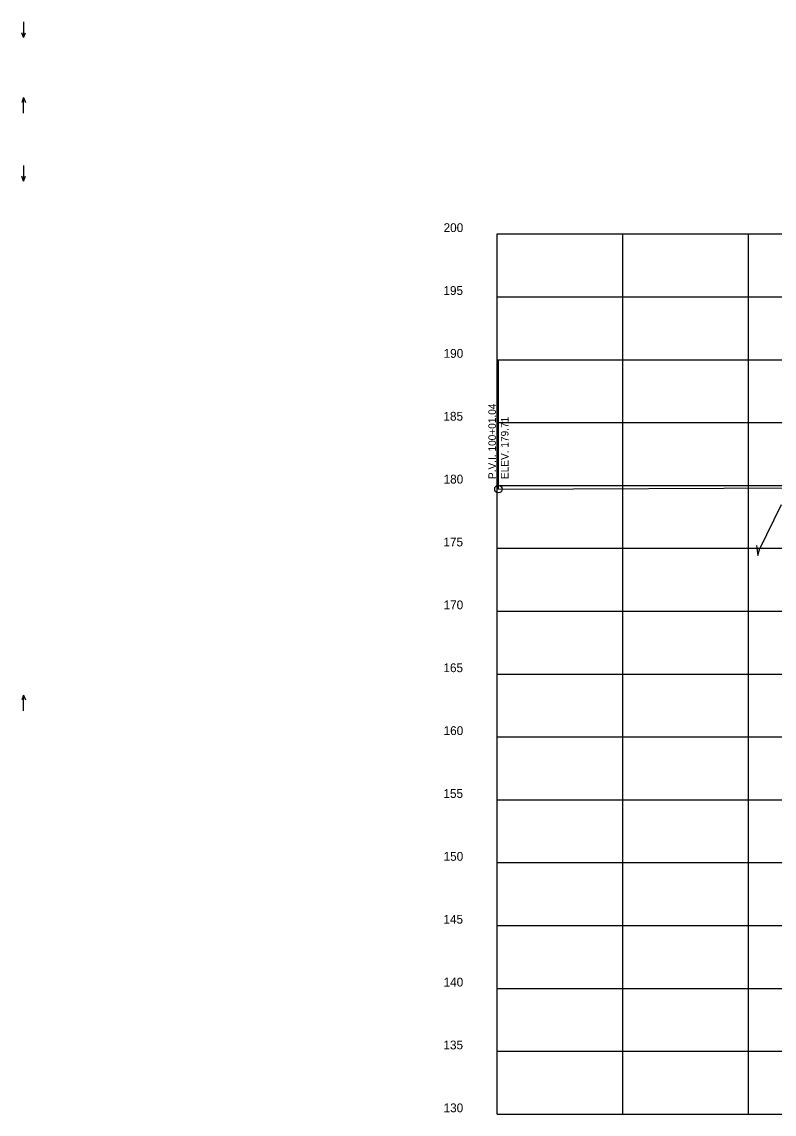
# Model space of a CAD drawing. Extents: x 915787 to 919910, y 133456 to 136717.
# Drawn here: x 916593 to 917192, y 135095 to 135964 of the extents above; entities that cross this region are included whole.
import ezdxf

# ---------------------------------------------------------------- set-up
doc = ezdxf.new("R2010")
doc.units = 0
for name, color, linetype in [('R_Axis', 7, 'Continuous'), ('R_Axis Annot', 7, 'Continuous'), ('R_Exist Surface', 7, 'Continuous'), ('R_Grid', 7, 'Continuous'), ('R_Vert Alg', 7, 'Continuous'), ('R_Vert Alg Annot', 7, 'Continuous'), ('R_Water Annot', 7, 'Continuous')]:
    doc.layers.add(name, color=color, linetype=linetype)

msp = doc.modelspace()

# ---------------------------------------------------------------- linework, layer by layer
at = {"layer": 'R_Axis'}
for q in [(916971.67, 135794.96), (919871.67, 135094.96)]:
    msp.add_line((916971.67, 135094.96), q, dxfattribs=at)
at = {"layer": 'R_Exist Surface'}
msp.add_lwpolyline([(917178.02, 135547.16), (917179.21, 135539.34), (917180.4, 135543.95), (917197.96, 135579.87)], dxfattribs=at)
at = {"layer": 'R_Grid'}
for p, q in [((916971.67, 135794.96), (919871.67, 135794.96)), ((916971.67, 135794.96), (919871.67, 135794.96)), ((917071.67, 135094.96), (917071.67, 135794.96)), ((917171.67, 135094.96), (917171.67, 135794.96)), ((916971.67, 135744.96), (919871.67, 135744.96)), ((916971.67, 135694.96), (919871.67, 135694.96)), ((916971.67, 135644.96), (919871.67, 135644.96)), ((916971.67, 135594.96), (919871.67, 135594.96)), ((916971.67, 135544.96), (919871.67, 135544.96)), ((916971.67, 135494.96), (919871.67, 135494.96)), ((916971.67, 135444.96), (919871.67, 135444.96)), ((916971.67, 135394.96), (919871.67, 135394.96)), ((916971.67, 135344.96), (919871.67, 135344.96)), ((916971.67, 135294.96), (919871.67, 135294.96)), ((916971.67, 135244.96), (919871.67, 135244.96)), ((916971.67, 135194.96), (919871.67, 135194.96)), ((916971.67, 135144.96), (919871.67, 135144.96))]:
    msp.add_line(p, q, dxfattribs=at)
at = {"layer": 'R_Vert Alg'}
for q in [(916972.71, 135694.05), (917471.67, 135593.88)]:
    msp.add_line((916972.71, 135592.05), q, dxfattribs=at)
msp.add_circle((916972.71, 135592.05), 3, dxfattribs=at)
at = {"layer": 'R_Water Annot'}
for p, q in [((916594.88, 135963.63), (916594.88, 135951.06)), ((916594.88, 135951.06), (916593.48, 135954.91)), ((916594.88, 135951.06), (916596.28, 135954.91)), ((916594.88, 135903.46), (916593.48, 135899.62)), ((916594.88, 135890.9), (916594.88, 135903.46)), ((916594.88, 135903.46), (916596.28, 135899.62)), ((916594.88, 135849.52), (916594.88, 135836.95)), ((916594.88, 135836.95), (916593.48, 135840.79)), ((916594.88, 135836.95), (916596.28, 135840.79)), ((916594.88, 135428.22), (916593.48, 135424.37)), ((916594.88, 135415.65), (916594.88, 135428.22)), ((916594.88, 135428.22), (916596.28, 135424.37))]:
    msp.add_line(p, q, dxfattribs=at)

# ---------------------------------------------------------------- texts
at = {"layer": 'R_Axis Annot'}
for s, p in [('200', (916929.06, 135796.46)), ('200', (916929.06, 135796.46)), ('195', (916928.93, 135746.46)), ('190', (916929.06, 135696.46)), ('185', (916928.93, 135646.46)), ('180', (916929.06, 135596.46)), ('175', (916928.93, 135546.46)), ('170', (916929.06, 135496.46)), ('165', (916928.93, 135446.46)), ('160', (916929.06, 135396.46)), ('155', (916928.93, 135346.46)), ('150', (916929.06, 135296.46)), ('145', (916928.93, 135246.46)), ('140', (916929.06, 135196.46)), ('135', (916928.93, 135146.46)), ('130', (916929.06, 135096.46))]:
    msp.add_text(s, height=7, dxfattribs=at).set_placement(p)
at = {"layer": 'R_Vert Alg Annot'}
for s, p in [('P.V.I. 100+01.04', (916970.71, 135600.05)), ('ELEV. 179.71', (916980.71, 135600.05))]:
    msp.add_text(s, height=6, rotation=90, dxfattribs=at).set_placement(p)

doc.saveas('drawing.dxf')
